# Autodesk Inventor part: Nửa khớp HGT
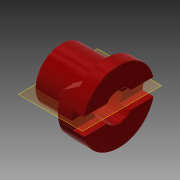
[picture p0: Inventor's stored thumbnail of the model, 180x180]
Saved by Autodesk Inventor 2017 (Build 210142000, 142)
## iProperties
Created: 2011-05
Part Number: Nửa khớp HGT
Document SubType Name: Modeling
Designer: Administrator
Density: 7.85 g/cm^3
Material: Steel
Mass: 38117.2 g
Surface Area: 2780.16 cm^2
Volume: 4855.7 cm^3
Sheet Metal Rule: Default
Appearance: Red
Author: Administrator
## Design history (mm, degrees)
sketch "Sketch1"
  geometry: L1 (0, 0)-(202, 0); L2 (0, 0)-(0, 90); L3 (0, 90)-(157, 90); L4 (157, 90)-(157, 125); L5 (157, 125)-(202, 125); L6 (202, 125)-(202, 0)
  constraints: 12 end point, 3 perpendicular, 1 horizontal, 1 parallel, 1 vertical
  dimensions: "d0" = 180 diameter of L3 L1; "d1" = 250 diameter of L5 L1; "d2" = 45 distance of L4.end L5.end; "d3" = 202 distance between parallel lines of L6 L2
revolve "Revolution1" sketch "Sketch1" stored, may be unused: angle "d4" = 90 deg
sketch "Sketch2"
  geometry: L1 (0, 90)-(0, -90) reference; L2 (0, -90)-(-157, -90) reference; L3 (-157, -90)-(-157, -125) reference; L4 (-157, -125)-(-202, -125) reference; L5 (-202, -125)-(-202, 125) reference; L6 (-202, 125)-(-157, 125) reference; L7 (-157, 125)-(-157, 90) reference; L8 (-157, 90)-(0, 90) reference; L9 (0, 0)-(-202, 0); L10 (-112, 60)-(-112, -60); L11 (-112, -60)-(-157, -85); L12 (-157, -85)-(-157, 85); L13 (-157, 85)-(-112, 60); L14 (0, -90)-(-157, -90) reference; L15 (-157, 90)-(0, 90) reference; L16 (0, -90)-(-157, -90) reference; L17 (-157, 90)-(0, 90) reference; L18 (-157, 90)-(-157, -90) reference; L19 (-157, -90)-(-157, -125) reference; L20 (-157, -125)-(-202, -125) reference; L21 (-202, -125)-(-202, 125) reference; L22 (-202, 125)-(-157, 125) reference; L23 (-157, 125)-(-157, 90) reference; L24 (0, 90)-(0, -90) reference; L25 (0, 90)-(0, -90) reference; L26 (-157, -125)-(-202, -125) reference; L27 (-202, -125)-(-202, 125) reference; L28 (-202, 125)-(-157, 125) reference; L29 (-157, -90)-(-157, -125) reference; L30 (-157, 125)-(-157, 90) reference
  constraints: 10 end point, 1 collinear, 1 midpoint, 1 parallel, 1 perpendicular
  dimensions: "d5" = 170 distance of L11.end L12.end; "d6" = 120 distance of L10.start L10.end; "d7" = 120 diameter of L10.end L9; "d8" = 170 diameter of L11.end L9; "d9" = 45 distance between parallel lines of L12 L10
extrude "Extrusion1" join sketch "Sketch2" stored distance "d10" = 5; taper "d11" = 0 deg
mirror "Mirror1"
sketch "Sketch3"
  geometry: L1 (30, -121.347)-(30, 121.347); L2 (-30, -121.347)-(-30, 121.347); A1 r 125 centre (0, 0) between (30, 121.347) and (-30, 121.347) reference
  constraints: 4 end point, 4 point on circle, 1 parallel, 1 vertical
  dimensions: "d12" = 30 distance from line of A1.centre L1 (= 0.5 x d13); "d13" = 60 distance between parallel lines of L2 L1
extrude "Extrusion2" cut sketch "Sketch3" distance "d14" = 40; taper "d15" = 0 deg
sketch "Sketch4" dims "d16" = 100
  geometry: L1 (0, 0)-(0, 82.037); C1 r 90 at (0, 0) reference; 2 further points
  constraints: 2 coincident, 2 end point, 1 point on line, 1 vertical, 1 vertical alignment, 2 other
extrude "Extrusion3" cut sketch "Sketch4" stored distance "d21" = 50; taper "d22" = 0 deg
chamfer "Chamfer1" distance "d25" = 2; stored, may be unused: second distance "d26" = 2, angle "d27" = 45 deg
chamfer "Chamfer2" distance "d28" = 2; stored, may be unused: second distance "d29" = 2, angle "d30" = 45 deg
fillet "Fillet3" dims "d31" = 5
fillet "Fillet4" dims "d32" = 5
sketch "Sketch5"
  geometry: L1 (14, -41.4)-(-14, -41.4); L2 (-14, -41.4)-(-14, -56.4); L3 (-14, -56.4)-(14, -56.4); L4 (14, -56.4)-(14, -41.4); C1 r 50 at (0, 0) reference; 2 further points
  constraints: 8 end point, 2 parallel, 1 horizontal, 1 midpoint, 1 perpendicular, 1 vertical alignment
  dimensions: "d33" = 28 distance of L3.end L2.end; "d34" = 6.4 distance edge to line of C1 L3; "d35" = 15 distance of L3.end L1.start
extrude "Extrusion4" cut sketch "Sketch5" stored distance "d36" = 10; taper "d37" = 0 deg
body "Solid1"
node "Project Cut Edges1"
node "Project Cut Edges2"
node "Project Cut Edges3"
other parameters: "Thickness" = 0.5, "KFactor" = 4.4, "BendRadius" = 0.5 (= Thickness), "BendReliefWidth" = 0.5 (= Thickness), "BendReliefDepth" = 0.25 (= 0.5 x Thickness), "CornerReliefSize" = 2 (= 4 x Thickness), "SeamGap" = 0.01, "MinimumRemnant" = 1 (= 2 x Thickness), "TransitionRadius" = 0.5 (= BendRadius), "JacobiRadiusSize" = 0.5 (= Thickness), "GapSize" = 0.5 (= Thickness)
